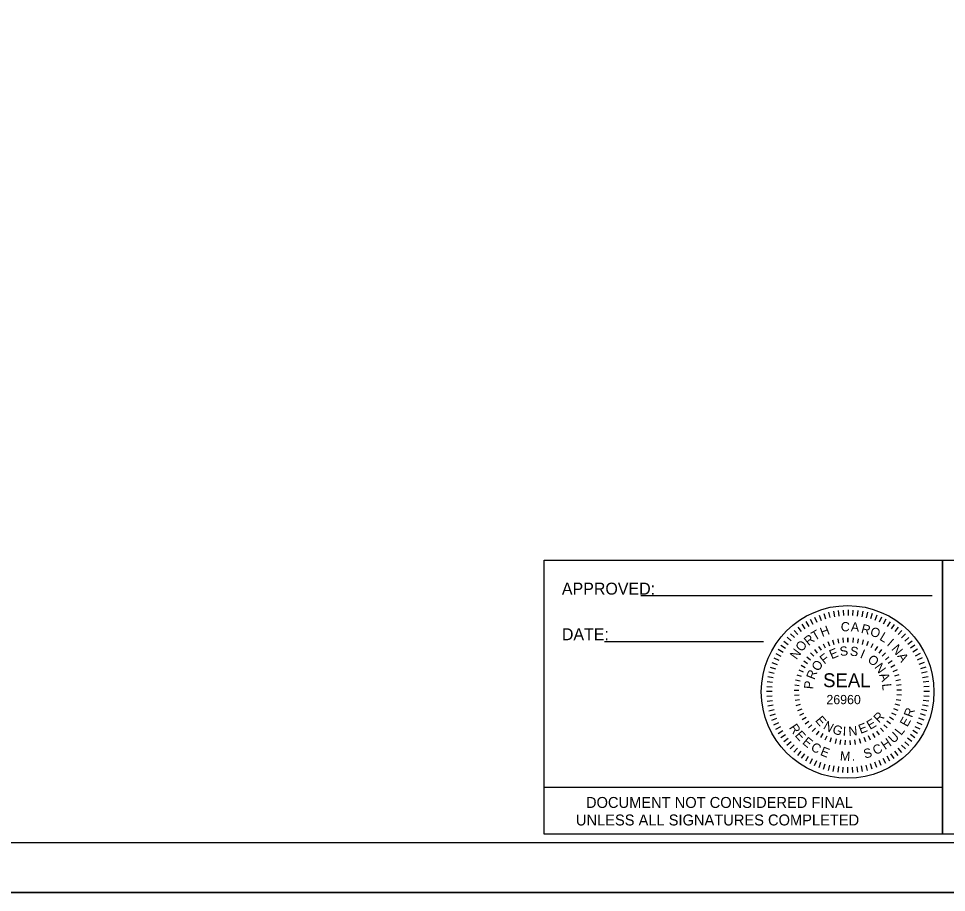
# Model space of a CAD drawing. Extents: x 762655 to 770567, y 650864 to 655190.
# Drawn here: x 765364.8 to 765830.7, y 652778.8 to 653217.5 of the extents above; entities that cross this region are included whole.
import ezdxf

# ---------------------------------------------------------------- set-up
doc = ezdxf.new("R2010")
doc.units = 0
for name, color, linetype in [('DEV BORDER CELL', 7, 'Continuous'), ('Scratch_Level_3', 7, 'Continuous'), ('Sheet Plot Border Outside CELL', 7, 'Continuous'), ('Sheet Sticker Exception Certification CELL', 7, 'Continuous'), ('Text', 7, 'Continuous')]:
    doc.layers.add(name, color=color, linetype=linetype)

msp = doc.modelspace()

# ---------------------------------------------------------------- linework, layer by layer
at = {"layer": 'DEV BORDER CELL'}
for p, q in [((765677.21, 652927.84), (765823.55, 652927.84)), ((765828.7, 652922.02), (765828.7, 652808.02)), ((765659.09, 652904.77), (765738.88, 652904.77))]:
    msp.add_line(p, q, dxfattribs=at)
for points in [[(766183.85, 653853.76), (764683.84, 653853.76), (764683.84, 652803.75), (766183.85, 652803.75)], [(765628.66, 652945.52), (765828.7, 652945.52), (765828.7, 652808.02), (765628.66, 652808.02)], [(765828.7, 652945.52), (765942.7, 652945.52), (765942.7, 652808.02), (765828.7, 652808.02)]]:
    msp.add_lwpolyline(points, close=True, dxfattribs=at)
msp.add_circle((765781.1, 652879.43), 43.34, dxfattribs=at)
at = {"layer": 'Scratch_Level_3'}
msp.add_lwpolyline([(764520.84, 653878.75), (766208.85, 653878.75), (766208.85, 652778.75), (764520.84, 652778.75)], close=True, dxfattribs=at)
at = {"layer": 'Sheet Plot Border Outside CELL'}
msp.add_lwpolyline([(764520.85, 652778.75), (766208.85, 652778.75), (766208.85, 653878.75), (764520.85, 653878.75)], close=True, dxfattribs=at)
at = {"layer": 'Sheet Sticker Exception Certification CELL'}
for p, q in [((765628.66, 652808.02), (765628.66, 652831.52)), ((765628.66, 652831.52), (765828.7, 652831.52)), ((765828.7, 652831.51), (765828.7, 652808.01)), ((765828.7, 652808.02), (765628.66, 652808.02))]:
    msp.add_line(p, q, dxfattribs=at)
at = {"layer": 'Text'}
for p, q in [((765773.92, 652919.92), (765774.42, 652917.18)), ((765776.36, 652920.29), (765776.69, 652917.52)), ((765778.82, 652920.51), (765778.98, 652917.73)), ((765781.29, 652920.58), (765781.28, 652917.8)), ((765783.75, 652920.5), (765783.59, 652917.72)), ((765786.21, 652920.28), (765785.88, 652917.51)), ((765788.65, 652919.91), (765788.15, 652917.17)), ((765762.29, 652915.92), (765763.58, 652913.45)), ((765764.51, 652916.99), (765765.65, 652914.45)), ((765766.79, 652917.94), (765767.78, 652915.33)), ((765769.12, 652918.75), (765769.95, 652916.08)), ((765771.51, 652919.4), (765772.16, 652916.7)), ((765791.06, 652919.39), (765790.4, 652916.68)), ((765793.45, 652918.72), (765792.62, 652916.06)), ((765795.78, 652917.91), (765794.78, 652915.31)), ((765798.06, 652916.96), (765796.91, 652914.43)), ((765800.28, 652915.88), (765798.98, 652913.42)), ((765756.07, 652911.91), (765757.78, 652909.71)), ((765758.06, 652913.37), (765759.64, 652911.07)), ((765760.13, 652914.71), (765761.57, 652912.32)), ((765802.43, 652914.67), (765800.98, 652912.29)), ((765804.5, 652913.32), (765802.91, 652911.03)), ((765806.48, 652911.86), (765804.77, 652909.67)), ((765750.68, 652906.84), (765752.76, 652904.99)), ((765752.37, 652908.64), (765754.34, 652906.66)), ((765754.17, 652910.33), (765756.02, 652908.24)), ((765776.1, 652906.15), (765776.54, 652903.87)), ((765778.67, 652906.52), (765778.89, 652904.21)), ((765781.27, 652906.65), (765781.27, 652904.33)), ((765781.27, 652904.33), (765781.27, 652906.65)), ((765783.87, 652906.52), (765783.65, 652904.21)), ((765786.45, 652906.14), (765786, 652903.86)), ((765808.38, 652910.28), (765806.53, 652908.19)), ((765810.18, 652908.58), (765808.21, 652906.62)), ((765811.87, 652906.78), (765809.78, 652904.94)), ((765747.63, 652902.96), (765749.92, 652901.37)), ((765749.09, 652904.94), (765751.29, 652903.23)), ((765766.5, 652902.26), (765767.77, 652900.31)), ((765768.75, 652903.57), (765769.82, 652901.52)), ((765771.11, 652904.67), (765771.98, 652902.52)), ((765773.57, 652905.53), (765774.23, 652903.3)), ((765788.97, 652905.52), (765788.31, 652903.29)), ((765791.43, 652904.65), (765790.55, 652902.5)), ((765793.79, 652903.55), (765792.71, 652901.49)), ((765796.03, 652902.23), (765794.76, 652900.28)), ((765813.45, 652904.88), (765811.25, 652903.17)), ((765814.91, 652902.9), (765812.62, 652901.32)), ((765745.07, 652898.74), (765747.54, 652897.44)), ((765746.29, 652900.89), (765748.67, 652899.44)), ((765760.67, 652897.1), (765762.45, 652895.6)), ((765762.45, 652899), (765764.07, 652897.34)), ((765764.4, 652900.73), (765765.85, 652898.91)), ((765798.14, 652900.7), (765796.68, 652898.88)), ((765800.08, 652898.97), (765798.46, 652897.3)), ((765801.85, 652897.06), (765800.08, 652895.56)), ((765816.25, 652900.82), (765813.86, 652899.38)), ((765817.46, 652898.67), (765814.99, 652897.38)), ((765742.23, 652891.91), (765744.9, 652891.07)), ((765743.04, 652894.24), (765745.65, 652893.24)), ((765743.99, 652896.51), (765746.53, 652895.37)), ((765757.72, 652892.82), (765759.74, 652891.69)), ((765759.09, 652895.03), (765761, 652893.71)), ((765803.44, 652894.99), (765801.52, 652893.67)), ((765804.8, 652892.78), (765802.78, 652891.65)), ((765818.54, 652896.45), (765816, 652895.31)), ((765819.48, 652894.17), (765816.87, 652893.18)), ((765741.57, 652889.52), (765744.27, 652888.86)), ((765755.63, 652888.05), (765757.84, 652887.34)), ((765756.56, 652890.49), (765758.69, 652889.56)), ((765805.96, 652890.44), (765803.83, 652889.52)), ((765806.88, 652888.01), (765804.67, 652887.29)), ((765820.29, 652891.83), (765817.62, 652891.01)), ((765820.95, 652889.45), (765818.24, 652888.79)), ((765740.68, 652884.67), (765743.44, 652884.34)), ((765741.05, 652887.11), (765743.79, 652886.61)), ((765754.51, 652882.98), (765756.81, 652882.7)), ((765754.95, 652885.54), (765757.21, 652885.04)), ((765807.56, 652885.5), (765805.29, 652885)), ((765807.99, 652882.93), (765805.69, 652882.65)), ((765821.46, 652887.04), (765818.72, 652886.54)), ((765821.83, 652884.6), (765819.07, 652884.26)), ((765740.37, 652879.74), (765743.16, 652879.74)), ((765740.45, 652882.21), (765743.23, 652882.04)), ((765754.32, 652880.38), (765756.63, 652880.32)), ((765754.38, 652877.78), (765756.69, 652877.94)), ((765808.18, 652880.33), (765805.86, 652880.28)), ((765822.05, 652882.14), (765819.27, 652881.97)), ((765822.12, 652879.67), (765819.34, 652879.67)), ((765740.45, 652877.27), (765743.23, 652877.44)), ((765740.67, 652874.82), (765743.43, 652875.15)), ((765754.69, 652875.2), (765756.98, 652875.58)), ((765805.52, 652875.62), (765807.81, 652875.23)), ((765808.12, 652877.73), (765805.8, 652877.9)), ((765821.82, 652874.74), (765819.06, 652875.08)), ((765822.05, 652877.2), (765819.27, 652877.37)), ((765741.03, 652872.38), (765743.77, 652872.87)), ((765741.55, 652869.96), (765744.26, 652870.62)), ((765755.25, 652872.65), (765757.49, 652873.26)), ((765756.05, 652870.17), (765758.22, 652871)), ((765757.09, 652867.79), (765759.17, 652868.82)), ((765805.38, 652867.75), (765803.31, 652868.78)), ((765806.43, 652870.13), (765804.26, 652870.95)), ((765807.24, 652872.6), (765805, 652873.21)), ((765820.93, 652869.89), (765818.22, 652870.55)), ((765821.45, 652872.3), (765818.71, 652872.8)), ((765742.21, 652867.58), (765744.88, 652868.41)), ((765743.01, 652865.25), (765745.62, 652866.24)), ((765743.96, 652862.97), (765746.5, 652864.1)), ((765758.35, 652865.52), (765760.32, 652866.73)), ((765759.83, 652863.37), (765761.67, 652864.78)), ((765802.64, 652863.33), (765800.79, 652864.74)), ((765804.12, 652865.47), (765802.15, 652866.7)), ((765818.5, 652862.9), (765815.97, 652864.04)), ((765819.46, 652865.18), (765816.85, 652866.17)), ((765820.26, 652867.51), (765817.6, 652868.34)), ((765745.04, 652860.74), (765747.51, 652862.04)), ((765746.25, 652858.59), (765748.63, 652860.03)), ((765761.5, 652861.38), (765763.2, 652862.96)), ((765763.36, 652859.56), (765764.91, 652861.3)), ((765765.39, 652857.93), (765766.76, 652859.8)), ((765797.06, 652857.9), (765795.7, 652859.78)), ((765799.1, 652859.53), (765797.56, 652861.27)), ((765800.96, 652861.34), (765799.26, 652862.92)), ((765816.21, 652858.53), (765813.83, 652859.97)), ((765817.43, 652860.68), (765814.96, 652861.97)), ((765747.59, 652856.52), (765749.88, 652858.1)), ((765749.05, 652854.53), (765751.24, 652856.24)), ((765767.57, 652856.5), (765768.75, 652858.5)), ((765769.87, 652855.29), (765770.85, 652857.39)), ((765772.28, 652854.3), (765773.06, 652856.49)), ((765775.32, 652855.81), (765774.76, 652853.56)), ((765777.33, 652853.05), (765777.67, 652855.35)), ((765779.92, 652852.8), (765780.03, 652855.12)), ((765782.52, 652852.8), (765782.42, 652855.11)), ((765785.11, 652853.05), (765784.78, 652855.34)), ((765787.67, 652853.54), (765787.11, 652855.8)), ((765790.16, 652854.28), (765789.39, 652856.48)), ((765792.58, 652855.27), (765791.6, 652857.37)), ((765794.89, 652856.47), (765793.71, 652858.48)), ((765813.4, 652854.47), (765811.21, 652856.19)), ((765814.87, 652856.45), (765812.58, 652858.04)), ((765750.63, 652852.63), (765752.71, 652854.47)), ((765752.32, 652850.83), (765754.29, 652852.8)), ((765754.11, 652849.14), (765755.96, 652851.22)), ((765808.33, 652849.09), (765806.48, 652851.17)), ((765810.12, 652850.78), (765808.16, 652852.75)), ((765811.82, 652852.57), (765809.74, 652854.42)), ((765756.01, 652847.55), (765757.73, 652849.74)), ((765758, 652846.09), (765759.58, 652848.38)), ((765760.07, 652844.75), (765761.51, 652847.13)), ((765762.22, 652843.53), (765763.52, 652846)), ((765800.21, 652843.49), (765798.92, 652845.96)), ((765802.36, 652844.71), (765800.92, 652847.09)), ((765804.44, 652846.05), (765802.86, 652848.34)), ((765806.42, 652847.51), (765804.71, 652849.7)), ((765764.44, 652842.45), (765765.58, 652844.99)), ((765766.72, 652841.5), (765767.71, 652844.11)), ((765769.05, 652840.69), (765769.88, 652843.35)), ((765771.43, 652840.03), (765772.1, 652842.73)), ((765773.84, 652839.51), (765774.35, 652842.25)), ((765776.28, 652839.14), (765776.62, 652841.9)), ((765778.74, 652838.91), (765778.91, 652841.69)), ((765781.21, 652838.83), (765781.21, 652841.62)), ((765783.68, 652838.9), (765783.52, 652841.68)), ((765786.14, 652839.13), (765785.81, 652841.89)), ((765788.58, 652839.49), (765788.08, 652842.23)), ((765790.99, 652840.01), (765790.33, 652842.71)), ((765793.37, 652840.67), (765792.55, 652843.33)), ((765795.71, 652841.47), (765794.72, 652844.08)), ((765797.99, 652842.42), (765796.85, 652844.96))]:
    msp.add_line(p, q, dxfattribs=at)

# ---------------------------------------------------------------- texts
at = {"layer": 'DEV BORDER CELL'}
for s, p in [('APPROVED:  ', (765637.63, 652928.27)), ('DATE:  ', (765637.63, 652905.36))]:
    msp.add_text(s, height=6, dxfattribs=at).set_placement(p)
at = {"layer": 'Sheet Sticker Exception Certification CELL'}
for s, p in [('DOCUMENT NOT CONSIDERED FINAL', (765649.73, 652821.18)), ('UNLESS ALL SIGNATURES COMPLETED', (765644.66, 652812.38))]:
    msp.add_text(s, height=5.5, dxfattribs=at).set_placement(p)
at = {"layer": 'Text'}
for s, height, rotation, p in [('T', 4.64, 30.4466, (765764.59, 652904.96)), ('H', 4.64, 21.0146, (765768.33, 652906.97)), ('C', 4.64, 357.3039, (765777.56, 652909.95)), ('A', 4.64, 357.3039, (765782.63, 652909.85)), ('R', 4.64, 345.2946, (765787.55, 652909.16)), ('O', 4.64, 342.2378, (765792.04, 652907.82)), ('R', 4.64, 38.6075, (765761.47, 652902.36)), ('L', 4.64, 329.1015, (765796.76, 652905.75)), ('I', 4.64, 319.5261, (765800.5, 652903.05)), ('N', 4.64, 53.6237, (765755.43, 652895.32)), ('O', 4.64, 51.6643, (765758.1, 652899.24)), ('E', 4.64, 22.8914, (765773.08, 652895.76)), ('S', 4.64, 7.5951, (765777.44, 652897.35)), ('S', 4.64, 352.2989, (765782.07, 652897.73)), ('N', 4.64, 310.2316, (765802.82, 652900.86)), ('F', 4.64, 38.1876, (765769.36, 652893.14)), ('I', 4.64, 337.0026, (765787, 652896.73)), ('O', 4.64, 321.7064, (765790.74, 652894.92)), ('A', 4.64, 300.4641, (765805.88, 652897.44)), ('O', 4.64, 53.4838, (765766.27, 652889.4)), ('N', 4.64, 306.4101, (765794.31, 652891.81)), ('R', 4.64, 68.7801, (765764.43, 652885.24)), ('SEAL', 6.965, 359.947, (765768.77, 652881.81)), ('A', 4.64, 291.1139, (765796.86, 652888)), ('P', 4.64, 84.0763, (765763.73, 652880.64)), ('L', 4.64, 275.8176, (765798.35, 652883.41)), ('26960', 4.64, 359.947, (765770.45, 652873.27)), ('R', 4.64, 44.5119, (765796.77, 652863.52)), ('R', 4.64, 69.6194, (765813.44, 652866.23)), ('E', 4.64, 310.0171, (765764.6, 652864.99)), ('N', 4.64, 330.8721, (765768.5, 652861.11)), ('E', 4.64, 20.7549, (765787.59, 652858.32)), ('E', 4.64, 30.7408, (765792.35, 652860.29)), ('E', 4.64, 60.9466, (765811.05, 652861.54)), ('R', 4.64, 303.882, (765751.5, 652861.45)), ('E', 4.64, 311.9538, (765754.37, 652857.44)), ('G', 4.64, 339.6384, (765773.04, 652858.93)), ('I', 4.64, 357.7332, (765778.56, 652857.44)), ('N', 4.64, 5.3628, (765781.71, 652857.29)), ('U', 4.64, 43.2714, (765804.09, 652853.31)), ('L', 4.64, 52.154, (765807.98, 652857.27)), ('E', 4.64, 320.5966, (765758.02, 652853.65)), ('H', 4.64, 34.3888, (765799.86, 652850.19)), ('C', 4.64, 329.2691, (765762.2, 652850.46)), ('E', 4.64, 338.2416, (765767.01, 652847.84)), ('S', 4.64, 16.5636, (765789.82, 652845.87)), ('C', 4.64, 25.5662, (765795.01, 652847.63)), ('M', 4.64, 356.0369, (765777.12, 652845.03)), ('.', 4.64, 3.7793, (765783.18, 652844.88))]:
    msp.add_text(s, height=height, rotation=rotation, dxfattribs=at).set_placement(p)

doc.saveas('drawing.dxf')
